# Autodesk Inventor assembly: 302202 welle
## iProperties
Created: 2006-12
Part Number: 302202 welle
Cost Center: 0 kg
Document SubType Name: Assembly
Designer: Martin
Authority: 0 mm^3
Mass: 5101.89 g
Surface Area: 1514.07 cm^2
Volume: 651.121 cm^3
Density: 7.83555 g/cm^3
SaveDate: 2004-08-02
SaveTime: 16:43
TotalMass: 0 kg
TotalVolume: 0 mm^3
Author: Martin
